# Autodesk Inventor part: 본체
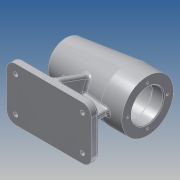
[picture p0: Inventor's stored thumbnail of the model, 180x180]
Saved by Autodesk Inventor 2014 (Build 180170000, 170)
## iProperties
Created: 2018-09
Part Number: 본체
Material: 알루미늄 6061
Document SubType Name: Modeling
Designer: kb542
Density: 2.71 g/cm^3
Appearance: 알루미늄 - 평지
Mass: 737.08 g
Surface Area: 664.757 cm^2
Volume: 271.985 cm^3
Author: kb542
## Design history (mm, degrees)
sketch "스케치2"
  geometry: L1 (-56, -35)-(56, -35); L2 (56, -35)-(56, 35); L3 (56, 35)-(-56, 35); L4 (-56, 35)-(-56, -35); L5 (-56, -35)-(56, 35); L6 (56, -35)-(-56, 35); 3 further points
  constraints: 12 end point, 3 midpoint, 2 parallel, 1 coincident, 1 horizontal, 1 perpendicular
  dimensions: "d0" = 112 distance of L2.end L3.end; "d1" = 70 distance between parallel lines of L1 L3
extrude "돌출1" new body sketch "스케치2" distance "d2" = 10; taper "d3" = 0 deg
sketch "스케치5"
  geometry: L1 (-52.27, 98.144)-(28, 108); L2 (28, 108)-(56, 108); L3 (56, 108)-(56, 74); L4 (56, 74)-(-56, 74); L5 (56, 0)-(56, 10) reference; L6 (-56, 0)-(56, 0) reference; A1 r 80 centre (24, 74) between (-52.27, 98.144) and (-56, 74); 1 further point
  constraints: 8 end point, 2 perpendicular, 2 point on circle, 1 centre point, 1 horizontal, 1 point on line
  dimensions: "d4" = 0 distance between parallel lines of L3 L5; "d5" = 28 distance of L1.end L2.end; "d6" = 112 distance from line of L3 L4.end; "d7" = 7 deg angle of L2 L1; "d8" = 80 radius of A1; "d9" = 68 diameter of L2 L4; "d10" = 74 distance between parallel lines of L4 L6
revolve "회전1" sketch "스케치5" stored, may be unused: angle "d11" = 90 deg
sketch "스케치6"
  geometry: L1 (-38, 10)-(-27.436, 49.426); L2 (38, 43.205)-(38, 10); L3 (56, 10)-(-56, 10) reference; L4 (56, 0)-(56, 10) reference; L5 (-56, 0)-(-56, 10) reference; L6 (-56, 10)-(56, 10) reference; L7 (-38, 10)-(38, 10); L8 (-27.436, 49.426)-(38, 43.205); 2 further points
  constraints: 8 end point, 2 point on line, 1 collinear, 1 vertical
  dimensions: "d12" = 18 distance between parallel lines of L4 L2; "d13" = 18 distance from line of L1.start L5; "d14" = 105 deg angle of L1 L3
extrude "돌출2" join sketch "스케치6" stored distance "d15" = 8; taper "d16" = 0 deg
sketch "스케치7"
  geometry: L1 (10, -35)-(0, -35) reference; L2 (0, -35)-(0, 35) reference; L3 (0, 35)-(10, 35) reference; L4 (10, 35)-(10, 4) reference; L5 (10, 4)-(43.701, 4) reference; L6 (43.701, -4)-(10, -4) reference; L7 (10, -4)-(10, -35) reference; L8 (10, 35)-(56.666, 18.015); L9 (10, -35)-(56.666, -18.015); L10 (10, 35)-(10, -35); L11 (10, -35)-(10, 35) reference; L12 (10, -35)-(0, -35) reference; L13 (0, -35)-(0, 35) reference; L14 (0, 35)-(10, 35) reference; L15 (10, 35)-(10, 4) reference; L16 (10, 4)-(43.701, 4) reference; L17 (43.701, -4)-(10, -4) reference; L18 (10, -4)-(10, -35) reference; A1 r 30.562 centre (74, 0) between (43.701, -4) and (43.701, 4) reference; A2 r 30.562 centre (74, 0) between (43.701, -4) and (43.701, 4) reference; A3 r 25 centre (74, 0) between (56.666, 18.015) and (56.666, -18.015); 4 further points
  constraints: 6 end point, 4 point on circle, 2 point on line, 1 centre point, 1 coincident, 1 collinear
  dimensions: "d17" = 110 deg angle of L8 L10; "d18" = 110 deg angle of L9 L7; "d21" = 50 diameter of A3
extrude "돌출5" join sketch "스케치7" stored distance "d24" = 8; taper "d25" = 0 deg
sketch "스케치8"
  geometry: L1 (-56, 74)-(76.223, 74); L2 (-50, 74)-(-50, 84.5); L3 (-50, 84.5)-(-47, 84.5); L4 (-43, 91.5)-(-25, 91.5); L5 (-25, 91.5)-(-25, 95); L6 (-25, 95)-(-13, 95); L7 (-13, 95)-(-13, 98); L8 (-13, 98)-(41, 98); L9 (41, 98)-(41, 95); L10 (41, 95)-(56, 95); L11 (56, 95)-(56, 74); L12 (-43, 91.5)-(-43, 90); L13 (-43, 90)-(-47, 90); L14 (-47, 90)-(-47, 84.5); L15 (56, 0)-(-56, 0) reference; L16 (56, 0)-(56, 10) reference; L17 (56, 40)-(56, 108) reference; 2 further points
  constraints: 28 end point, 9 parallel, 3 perpendicular, 3 point on line, 1 horizontal, 1 midpoint
  dimensions: "d28" = 42 diameter of L10 L1; "d29" = 48 diameter of L8 L1; "d31" = 54 distance between parallel lines of L9 L7; "d32" = 42 diameter of L6 L1; "d33" = 12 distance between parallel lines of L7 L5; "d37" = 3 distance between parallel lines of L14 L2; "d38" = 21 diameter of L3 L1; "d39" = 32 diameter of L13 L1; "d40" = 35 diameter of L4 L1; "d41" = 4 distance between parallel lines of L12 L14; "d42" = 18 distance of L4.start L4.end; "d45" = 0 distance between parallel lines of L16 L11; "d46" = 15 distance of L9.end L10.end
revolve "회전2" sketch "스케치8" stored, may be unused: angle "d47" = 90 deg
sketch "스케치9" dims "d48" = 52
  geometry: C1 r 34 at (0, 0) reference; 3 further points
  constraints: 1 coincident, 1 vertical alignment, 2 other
hole "구멍1" sketch "스케치9" at (0, 26) diameter "d49" = 3.242; stored, may be unused: countersink angle "d53" = 90 deg, drill point angle "d55" = 118 deg; dims "d50" = 8, "d51" = 4, "d52" = 2, "d54" = 11
fillet "모깎기1" dims "d59" = 12
hole "구멍2" diameter "d62" = 5.5; stored, may be unused: countersink angle "d66" = 90 deg, drill point angle "d68" = 118 deg; dims "d60" = 10, "d61" = 10, "d63" = 8, "d64" = 9.5, "d65" = 5.4, "d67" = 11
fillet "모깎기2" dims "d69" = 3
fillet "모깎기3" dims "d70" = 3
fillet "모깎기4" dims "d71" = 3
fillet "모깎기5" dims "d72" = 3
fillet "모깎기6" dims "d73" = 3
fillet "모깎기7" dims "d74" = 0.3
fillet "모깎기8" dims "d75" = 3
fillet "모깎기9" dims "d76" = 3
chamfer "모따기1" distance "d77" = 1; stored, may be unused: second distance "d78" = 2, angle "d79" = 45 deg
sketch "스케치10"
  geometry: L1 (0, 0)-(88, 0) reference; L2 (100, 0)-(100, 7) reference; 2 further points
  constraints: 1 other
  dimensions: "d80" = 56 distance from line of point (44, 3) L2; "d81" = 3 distance from line of L1 point (44, 3)
feature "엠보싱1" sketch "스케치10" dims "d0" = 112, "d1" = 70, "d82" = 0.5, "d83" = 0
node "솔리드1"
pattern_circular "원형 패턴1" dims angle "d57" = 360 deg
mirror "대칭1"
mirror "대칭2"
node "절단 모서리 투영1"
node "절단 모서리 투영2"
